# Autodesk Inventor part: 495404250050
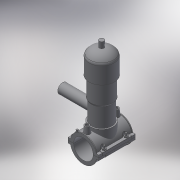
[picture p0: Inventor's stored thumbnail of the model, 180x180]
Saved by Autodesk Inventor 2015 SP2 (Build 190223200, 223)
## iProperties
Created: 2017-07
Part Number: 495404250050
Material: Generic
Description: PLASSON TAPPING VALVE 250-50
Document SubType Name: Modeling
Designer: KIM
Density: 1 g/cm^3
Appearance: Default
Author: KIM
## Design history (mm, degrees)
derived "495404-4954S4.ipt"
feature "Solid1::495404-4954S4.ipt"
feature "Solid2::495404-4954S4.ipt"
tag "TaggingFeature1"
body "Solid1"
body "Solid2"
other parameters: "B_" = 252, "H_" = 152, "L_" = 176, "d_t" = 6, "H_1" = 51, "H_2" = 244, "d148" = 3.75, "d160" = 3.75, "d169" = 3.75, "d192" = 8.5, "d2" = 327.6, "d3" = 62.5, "d4" = 176, "d5" = 0, "d6" = 0.1, "d8" = 0, "d19" = 6, "d20" = 6, "d21" = 105.6, "d23" = 0, "d24" = 52.8, "d26" = 0, "d27" = 3, "d28" = 3, "d29" = 3, "d30" = 83.33333, "d31" = 6, "d32" = 0, "d33" = 0, "d34" = 0.6, "d40" = 152.1, "d47" = 197.25, "d70" = 15, "d72" = 0, "d73" = 6, "d75" = 5, "d76" = 0, "d77" = 12.5, "d78" = 155, "d79" = 15, "d80" = 70.4, "d82" = 5 deg, "d84" = 4, "d85" = 14, "d86" = 0, "d87" = 3, "d88" = 0, "d89" = 1, "d90" = 1, "d91" = 140.8, "d92" = 0, "d93" = 0.5, "d94" = 131.57895, "d96" = 301.275, "d97" = 3.52, "d98" = 0, "d120" = 140 deg, "d121" = 24.228, "d122" = 20 deg, "d123" = 585, "d124" = 175.5, "d126" = 0, "d143" = 257.5, "d145" = 32.69231, "d149" = 3.75, "d150" = 35.96154, "d153" = 176, "d154" = 0, "d156" = 146.25, "d157" = 160 deg, "d159" = 8.5, "d161" = 3.75, "d162" = 105.6, "d163" = 0, "d164" = 125, "d167" = 25, "d168" = 142.68293, "d170" = 3.75, "d172" = 0, "d173" = 1, "d175" = 125, "d176" = 20 deg, "d177" = 17.5, "d178" = 42.5, "d180" = 0, "d183" = 17, "d184" = 14, "d185" = 57.2, "d186" = 57.2, "d187" = 146.25, "d188" = 12.75, "d189" = 17.5, "d190" = 0, "d191" = 219.375, "d193" = 8.5, "d194" = 4.4, "d195" = 90 deg, "d197" = 0, "d199" = 0, "d205" = 14.64, "d206" = 81.33333, "d207" = 244, "d208" = 224.48, "d209" = 207.4, "d210" = 200.08, "d211" = 146.4, "d212" = 85.4, "d213" = 65.88, "d214" = 73.2, "d216" = 21.96, "d217" = 70.76, "d218" = 80.52, "d222" = 0, "d223" = 292.5, "d224" = 152, "d225" = 51, "d229" = 152, "d230" = 0
